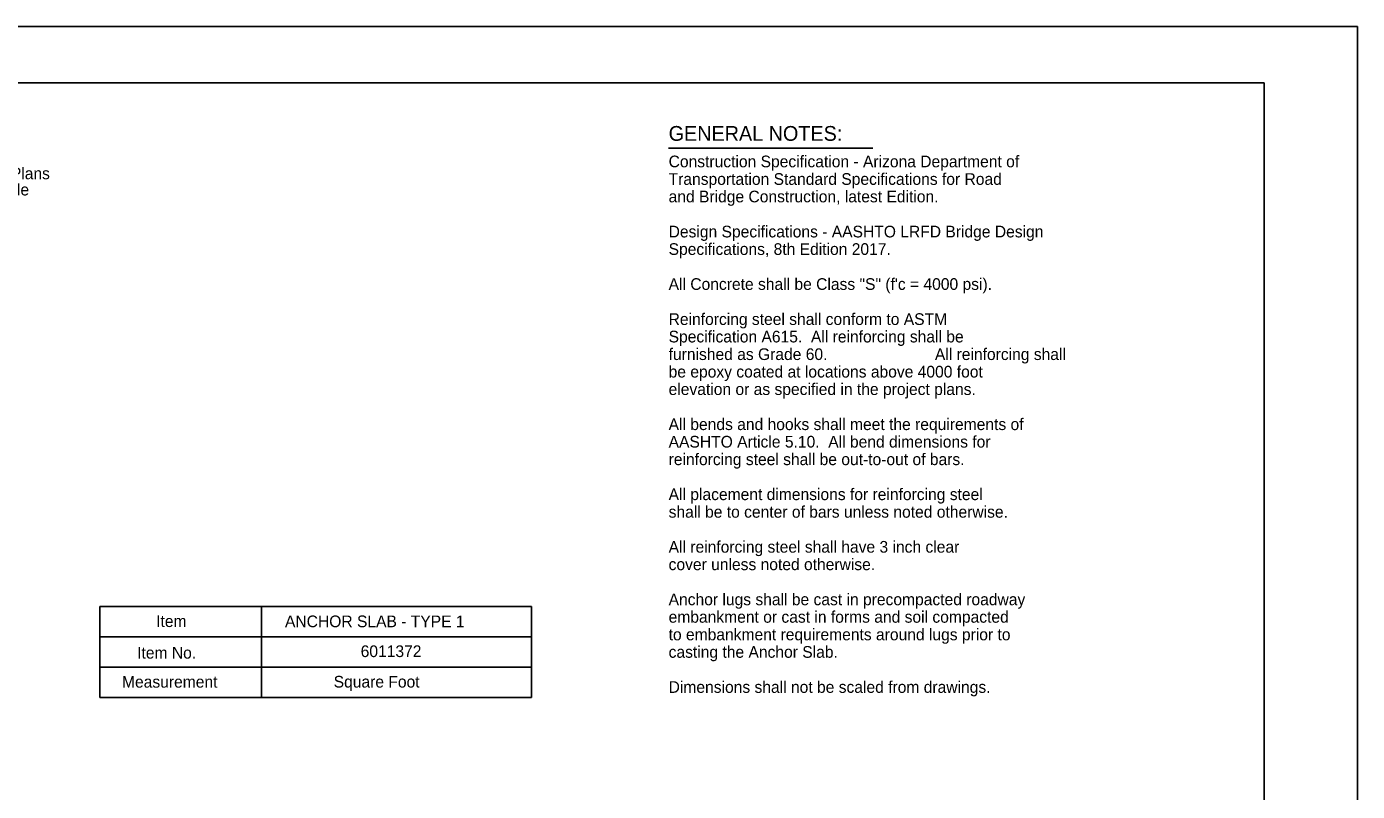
# Model space of a CAD drawing. Extents: x 0 to 2.83, y -0.03 to 1.83.
# Drawn here: x 1.349 to 2.833, y 0.981 to 1.833 of the extents above; entities that cross this region are included whole.
import ezdxf

# ---------------------------------------------------------------- set-up
doc = ezdxf.new("R2010")
doc.units = 0
for name, color, linetype in [('32', 7, 'Continuous'), ('57', 7, 'Continuous'), ('62', 7, 'Continuous'), ('63', 7, 'Continuous')]:
    doc.layers.add(name, color=color, linetype=linetype)

msp = doc.modelspace()

# ---------------------------------------------------------------- linework, layer by layer
at = {"layer": '32'}
msp.add_line((2.0651, 1.6977), (2.293, 1.6977), dxfattribs=at)
at = {"layer": '57'}
for p, q in [((1.4306, 1.1867), (1.9122, 1.1867)), ((1.4306, 1.1867), (1.4306, 1.0853)), ((1.6109, 1.1867), (1.6109, 1.0853)), ((1.9122, 1.1867), (1.9122, 1.0853)), ((1.4306, 1.1529), (1.9122, 1.1529)), ((1.4306, 1.1191), (1.9122, 1.1191)), ((1.4306, 1.0853), (1.9122, 1.0853))]:
    msp.add_line(p, q, dxfattribs=at)
at = {"layer": '62'}
msp.add_lwpolyline([(2.7292, 1.7708), (0.1042, 1.7708), (0.1042, 0.0624), (2.7292, 0.0624)], close=True, dxfattribs=at)
at = {"layer": '63'}
for p, q in [((0, 1.8333), (2.8333, 1.8333)), ((0, 1.8333), (2.8333, 1.8333)), ((0, 1.8333), (2.8333, 1.8333)), ((2.8333, 1.8333), (2.8333, 0)), ((2.8333, 1.8333), (2.8333, 0)), ((2.8333, 1.8333), (2.8333, 0))]:
    msp.add_line(p, q, dxfattribs=at)
msp.add_lwpolyline([(2.7292, 1.7708), (0.1042, 1.7708), (0.1042, 0.0624), (2.7292, 0.0624)], close=True, dxfattribs=at)

# ---------------------------------------------------------------- texts
at = {"layer": '57'}
for s, height, p in [('GENERAL NOTES:', 0.0165, (2.0651, 1.706)), ('Construction Specification - Arizona Department of', 0.013021, (2.0651, 1.6765)), ('See Project Plans', 0.012967, (1.2371, 1.6632)), ('Transportation Standard Specifications for Road', 0.013021, (2.0651, 1.6569)), ('for Skew angle', 0.012967, (1.2371, 1.6451)), ('and Bridge Construction, latest Edition.', 0.013021, (2.0651, 1.6374)), ('Design Specifications - AASHTO LRFD Bridge Design', 0.013021, (2.0651, 1.5983)), ('Specifications, 8th Edition 2017.', 0.013021, (2.0651, 1.5788)), ('All Concrete shall be Class "S" (f\'c = 4000 psi).', 0.013021, (2.0651, 1.5398)), ('Reinforcing steel shall conform to ASTM', 0.013021, (2.0651, 1.5007)), ('Specification A615.  All reinforcing shall be', 0.013021, (2.0651, 1.4812)), ('furnished as Grade 60. ', 0.013021, (2.0651, 1.4616)), ('All reinforcing shall', 0.013021, (2.3621, 1.4616)), ('be epoxy coated at locations above 4000 foot', 0.013021, (2.0651, 1.4421)), ('elevation or as specified in the project plans.', 0.013021, (2.0651, 1.4226)), ('All bends and hooks shall meet the requirements of', 0.013021, (2.0651, 1.3835)), ('AASHTO Article 5.10.  All bend dimensions for ', 0.013021, (2.0651, 1.364)), ('reinforcing steel shall be out-to-out of bars.', 0.013021, (2.0651, 1.3444)), ('All placement dimensions for reinforcing steel ', 0.013021, (2.0651, 1.3054)), ('shall be to center of bars unless noted otherwise.', 0.013021, (2.0651, 1.2858)), ('All reinforcing steel shall have 3 inch clear', 0.013021, (2.0651, 1.2468)), ('cover unless noted otherwise.', 0.013021, (2.0651, 1.2273)), ('Anchor lugs shall be cast in precompacted roadway', 0.013021, (2.0651, 1.1882)), ('Item', 0.01302, (1.4935, 1.1639)), ('ANCHOR SLAB - TYPE 1', 0.013021, (1.6372, 1.1637)), ('embankment or cast in forms and soil compacted', 0.013021, (2.0651, 1.1687)), ('to embankment requirements around lugs prior to', 0.013021, (2.0651, 1.1491)), ('6011372', 0.01302, (1.7216, 1.1304)), ('casting the Anchor Slab.', 0.013021, (2.0651, 1.1296)), ('Item No.', 0.01302, (1.4723, 1.1287)), ('Measurement', 0.013021, (1.4554, 1.0963)), ('Square Foot', 0.013021, (1.6915, 1.0964)), ('Dimensions shall not be scaled from drawings.', 0.013021, (2.0651, 1.0905))]:
    msp.add_text(s, height=height, dxfattribs=at).set_placement(p)

doc.saveas('drawing.dxf')
